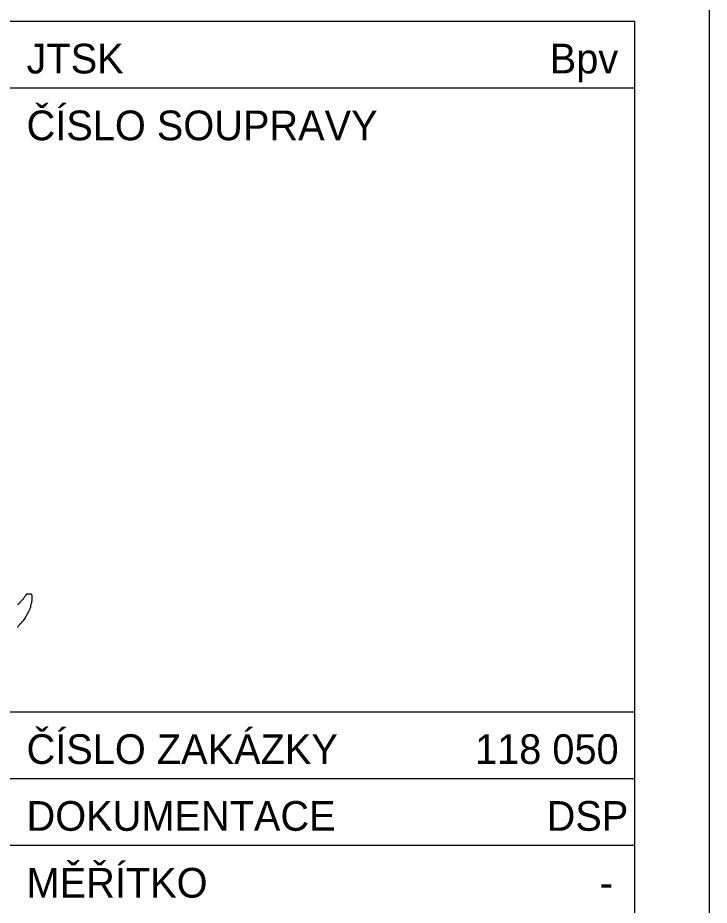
# Model space of a CAD drawing. Extents: x 0.683 to 0.91, y 84.096 to 84.393.
# Drawn here: x 0.8468 to 0.8934, y 84.1352 to 84.195 of the extents above; entities that cross this region are included whole.
import ezdxf

# ---------------------------------------------------------------- set-up
doc = ezdxf.new("R2010")
doc.units = 0
for name, color, linetype in [('koty_popisy_znacky', 7, 'Continuous'), ('pomocne_netiskne', 7, 'Continuous'), ('Smer reseni', 7, 'Continuous')]:
    doc.layers.add(name, color=color, linetype=linetype)

msp = doc.modelspace()

# ---------------------------------------------------------------- linework, layer by layer
at = {"layer": 'koty_popisy_znacky'}
msp.add_lwpolyline([(0.683364, 84.393234), (0.893364, 84.393234), (0.893364, 84.096234), (0.683364, 84.096234)], close=True, dxfattribs=at)
for points in [[(0.846185, 84.194734), (0.846185, 84.148234), (0.888364, 84.148234), (0.888364, 84.194734), (0.846185, 84.194734)], [(0.888364, 84.190234), (0.846185, 84.190234)], [(0.841185, 84.178234), (0.688364, 84.178234), (0.688364, 84.106234), (0.888364, 84.106234), (0.888364, 84.148234)], [(0.888364, 84.143734), (0.846185, 84.143734)], [(0.888364, 84.139234), (0.846185, 84.139234)]]:
    msp.add_lwpolyline(points, dxfattribs=at)
at = {"layer": 'pomocne_netiskne'}
msp.add_lwpolyline([(0.683364, 84.393234), (0.893364, 84.393234), (0.893364, 84.096234), (0.683364, 84.096234)], close=True, dxfattribs=at)
at = {"layer": 'Smer reseni'}
msp.add_lwpolyline([(0.846815, 84.153932), (0.846834, 84.153971), (0.846854, 84.154009), (0.846873, 84.154028), (0.846911, 84.154086), (0.84693, 84.154105), (0.84695, 84.154124), (0.846969, 84.154143), (0.846988, 84.154163), (0.847007, 84.154182), (0.847026, 84.154201), (0.847026, 84.15422), (0.847046, 84.15422), (0.847065, 84.154239), (0.847084, 84.154259), (0.847084, 84.154278), (0.847103, 84.154297), (0.847142, 84.154335), (0.847161, 84.154355), (0.84718, 84.154374), (0.847218, 84.154412), (0.847238, 84.154451), (0.847276, 84.154489), (0.847314, 84.154547), (0.847334, 84.154566), (0.847334, 84.154604), (0.847372, 84.154643), (0.847372, 84.154662), (0.847391, 84.1547), (0.84741, 84.15472), (0.847429, 84.154758), (0.847429, 84.154777), (0.847449, 84.154796), (0.847468, 84.154835), (0.847487, 84.154854), (0.847487, 84.154892), (0.847525, 84.154931), (0.847525, 84.15495), (0.847545, 84.154988), (0.847545, 84.155008), (0.847564, 84.155027), (0.847583, 84.155046), (0.847602, 84.155084), (0.847621, 84.155123), (0.847641, 84.155181), (0.84766, 84.155219), (0.847679, 84.155257), (0.847698, 84.155315), (0.847698, 84.155353), (0.847698, 84.155411), (0.847698, 84.15543), (0.847698, 84.155449), (0.847717, 84.155488), (0.847737, 84.155507), (0.847737, 84.155526), (0.847737, 84.155565), (0.847756, 84.155584), (0.847756, 84.155622), (0.847775, 84.155641), (0.847775, 84.155661), (0.847775, 84.15568), (0.847775, 84.155699), (0.847794, 84.155737), (0.847794, 84.155757), (0.847794, 84.155795), (0.847794, 84.155814), (0.847794, 84.155853), (0.847794, 84.155872), (0.847794, 84.15591), (0.847794, 84.155949), (0.847794, 84.155987), (0.847794, 84.156006), (0.847794, 84.156026), (0.847794, 84.156064), (0.847794, 84.156083), (0.847775, 84.156102), (0.847756, 84.156122), (0.847737, 84.156141), (0.847717, 84.15616), (0.847698, 84.15616), (0.847679, 84.15616), (0.847641, 84.156179), (0.847621, 84.156179), (0.847602, 84.156179), (0.847564, 84.156179), (0.847506, 84.156179), (0.847487, 84.156179), (0.847468, 84.156179), (0.847449, 84.156179), (0.84741, 84.15616), (0.847391, 84.156141), (0.847372, 84.156122), (0.847353, 84.156083), (0.847334, 84.156064), (0.847314, 84.156026), (0.847295, 84.156006), (0.847276, 84.155987), (0.847257, 84.155949), (0.847238, 84.15591), (0.847199, 84.155872), (0.847199, 84.155853), (0.847161, 84.155814), (0.847142, 84.155776), (0.847103, 84.155757), (0.847065, 84.155718), (0.847046, 84.155699), (0.847026, 84.155699), (0.846988, 84.155641), (0.846969, 84.155622), (0.84695, 84.155584), (0.846911, 84.155545), (0.846892, 84.155507), (0.846854, 84.155488), (0.846834, 84.155469), (0.846815, 84.155449)], dxfattribs=at)

# ---------------------------------------------------------------- texts
at = {"layer": 'koty_popisy_znacky'}
for s, p in [('JTSK', (0.847411, 84.191234)), ('Bpv', (0.882626, 84.191234)), ('ČÍSLO SOUPRAVY', (0.847411, 84.186734)), ('ČÍSLO ZAKÁZKY', (0.847411, 84.144734)), ('118 050', (0.877599, 84.144734)), ('DOKUMENTACE', (0.847411, 84.140234)), ('DSP', (0.882418, 84.140234)), ('MĚŘÍTKO     ', (0.847411, 84.135734)), ('-', (0.885992, 84.135734))]:
    msp.add_text(s, height=0.002, dxfattribs=at).set_placement(p)

doc.saveas('drawing.dxf')
